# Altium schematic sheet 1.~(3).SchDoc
size 420 x 297 mm
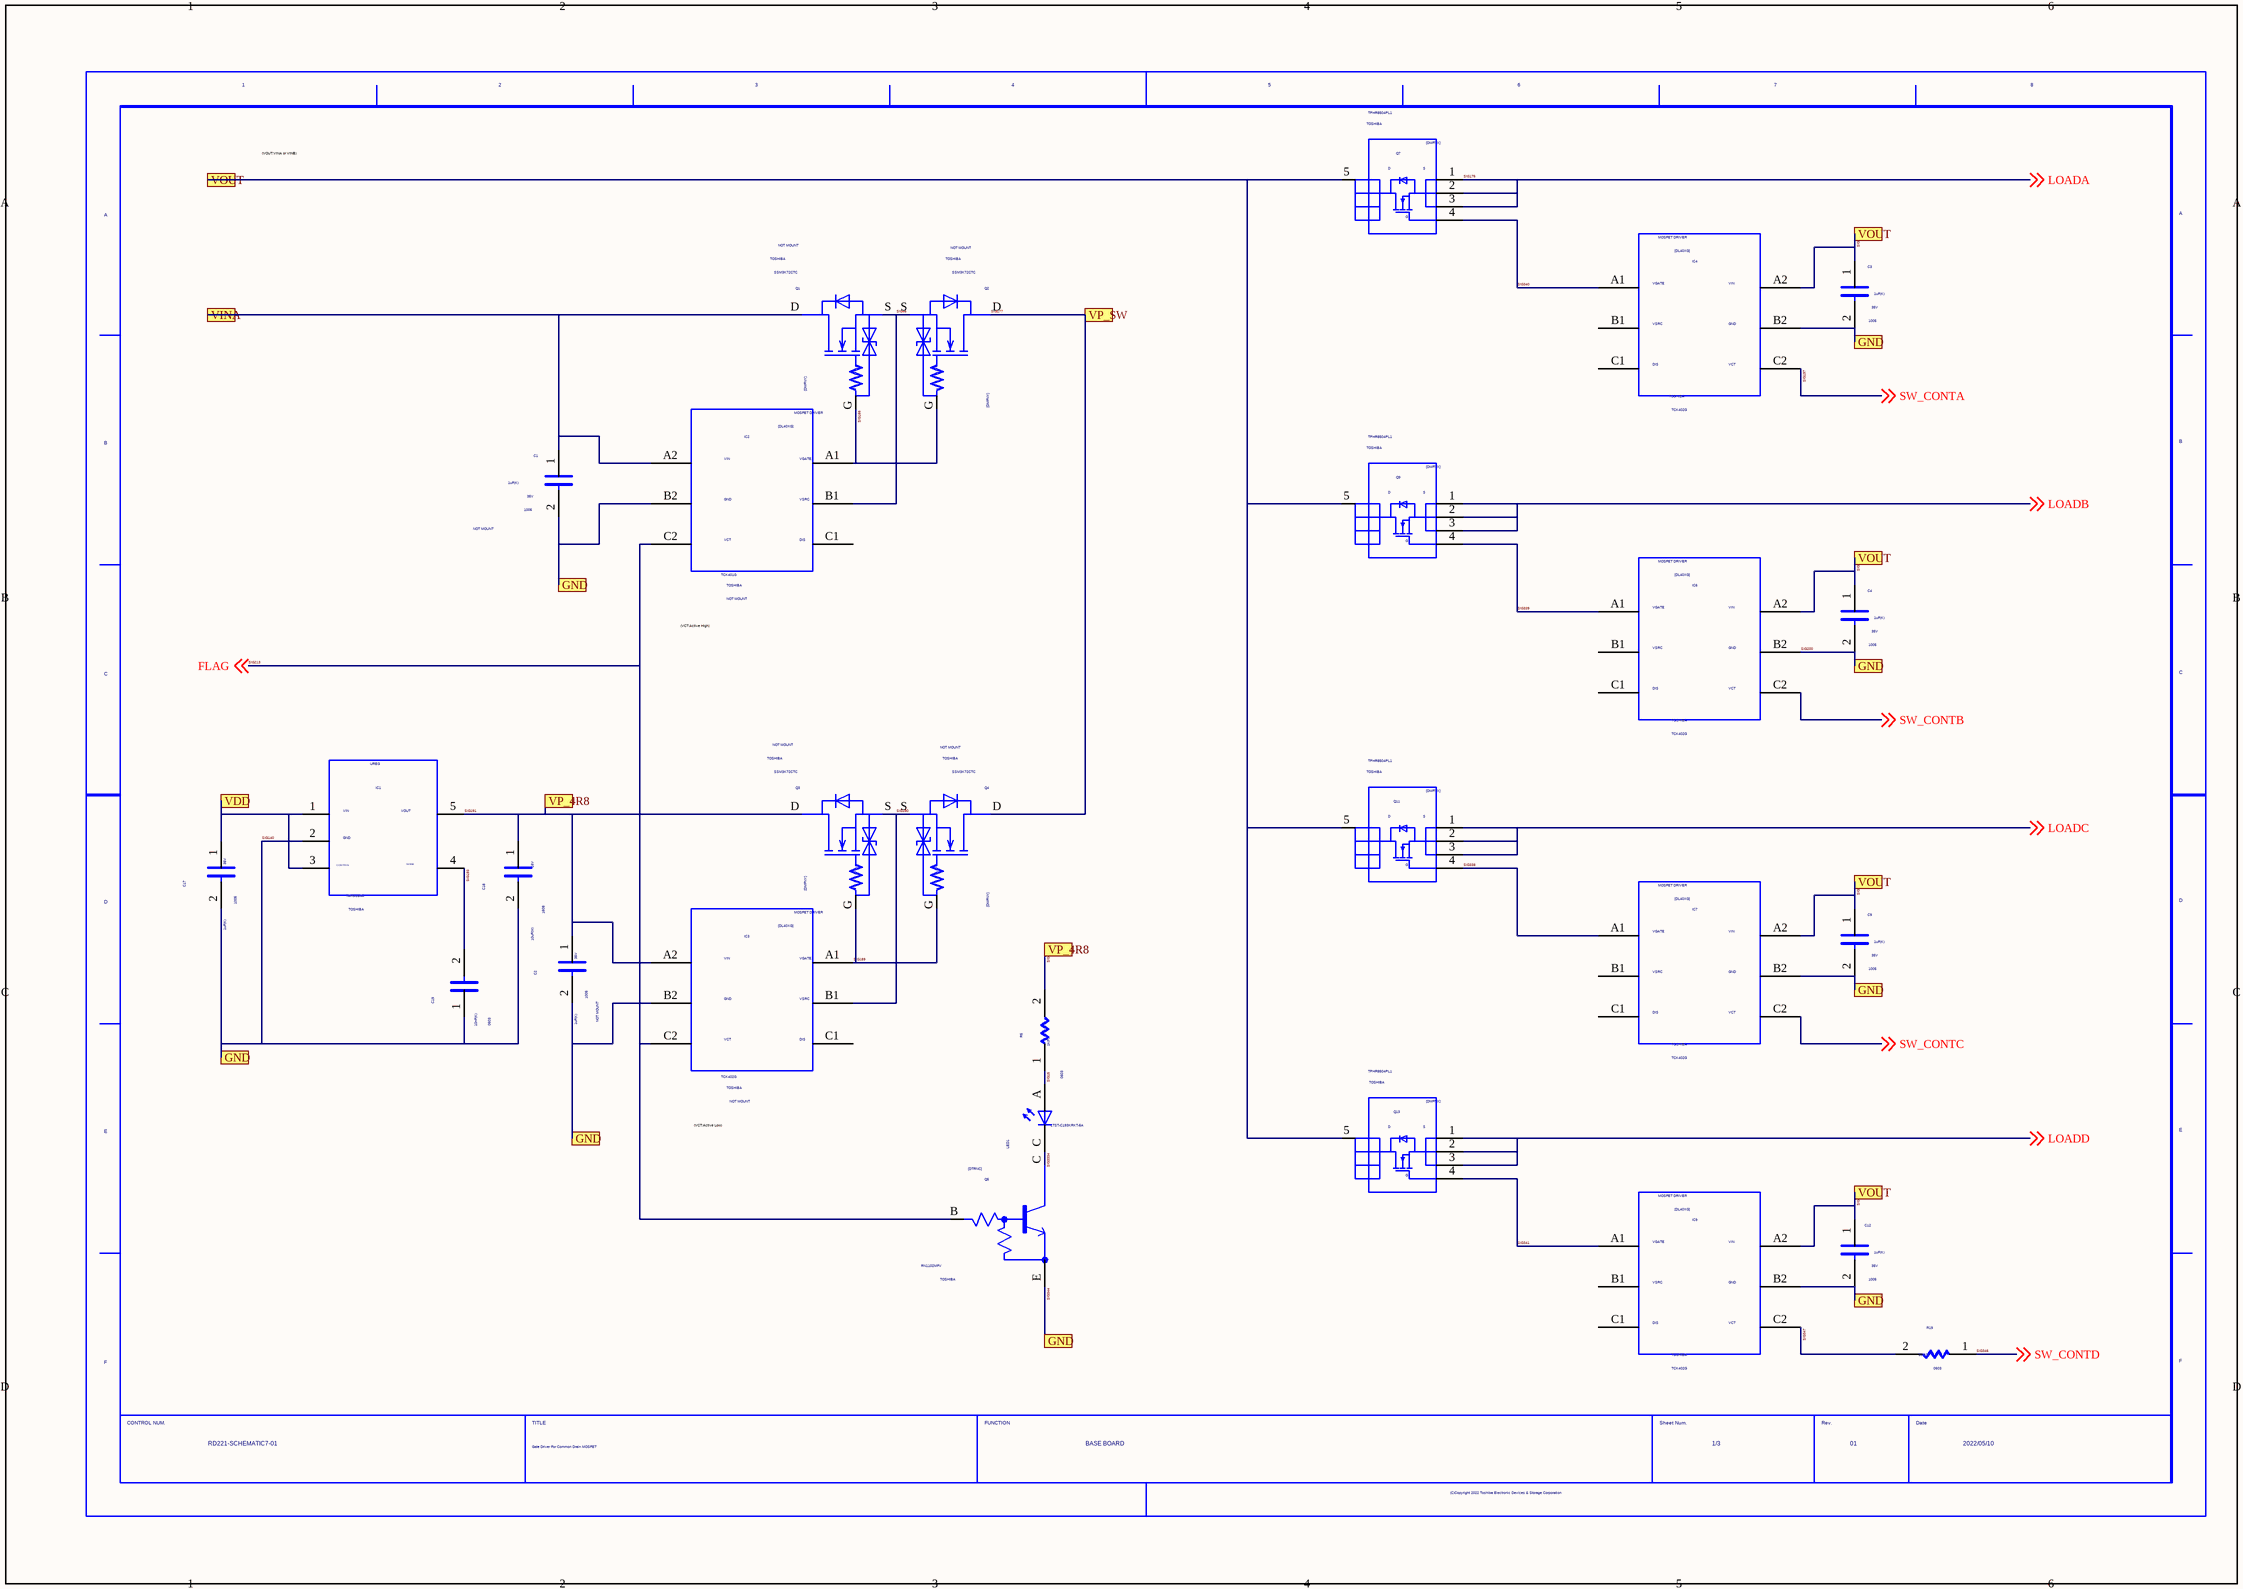
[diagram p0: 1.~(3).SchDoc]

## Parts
C1  NOTMOUNT: NOT MOUNT  SIZECODESMD: 1005  VAL2: 35V  VAL1: 1uF(K)  (hidden comment: DC)
C2  NOTMOUNT: NOT MOUNT  SIZECODESMD: 1005  VAL2: 35V  VAL1: 1uF(K)  (hidden comment: DC)
C3  SIZECODESMD: 1005  VAL2: 35V  VAL1: 1uF(K)  (hidden comment: DC)
C4  SIZECODESMD: 1005  VAL2: 35V  VAL1: 1uF(K)  (hidden comment: DC)
C9  SIZECODESMD: 1005  VAL2: 35V  VAL1: 1uF(K)  (hidden comment: DC)
C12  SIZECODESMD: 1005  VAL2: 35V  VAL1: 1uF(K)  (hidden comment: DC)
C17  SIZECODESMD: 1005  VAL2: 35V  VAL1: 1uF(K)  (hidden comment: DC)
C18  SIZECODESMD: 1608  VAL2: 16V  VAL1: 10uF(M)  (hidden comment: DC)
C19  SIZECODESMD: 0603  VAL1: 10nF(K)  (hidden comment: DC)
IC1  VAL1: TAR5SB48  USERCOMPTEXT3: TOSHIBA  (hidden comment: DL5SBXX)
IC2  NOTMOUNT: NOT MOUNT  VAL1: TCK401G  USERCOMPTEXT3: TOSHIBA  (hidden comment: DL40XG)
IC3  NOTMOUNT: NOT MOUNT  VAL1: TCK402G  USERCOMPTEXT3: TOSHIBA  (hidden comment: DL40XG)
IC4  VAL1: TCK402G  USERCOMPTEXT3: TOSHIBA  (hidden comment: DL40XG)
IC6  VAL1: TCK402G  USERCOMPTEXT3: TOSHIBA  (hidden comment: DL40XG)
IC7  VAL1: TCK402G  USERCOMPTEXT3: TOSHIBA  (hidden comment: DL40XG)
IC9  VAL1: TCK402G  USERCOMPTEXT3: TOSHIBA  (hidden comment: DL40XG)
LED1  VAL3: LTST-C193KRKT-5A  (hidden comment: DLED)
Q1  NOTMOUNT: NOT MOUNT  USERCOMPTEXT3: TOSHIBA  VAL1: SSM3K72CTC  (hidden comment: DMFNY)
Q2  NOTMOUNT: NOT MOUNT  USERCOMPTEXT3: TOSHIBA  VAL1: SSM3K72CTC  (hidden comment: DMFNY)
Q3  NOTMOUNT: NOT MOUNT  USERCOMPTEXT3: TOSHIBA  VAL1: SSM3K72CTC  (hidden comment: DMFNY)
Q4  NOTMOUNT: NOT MOUNT  USERCOMPTEXT3: TOSHIBA  VAL1: SSM3K72CTC  (hidden comment: DMFNY)
Q5  USERCOMPTEXT3: TOSHIBA  USERCOMPTEXT1: RN1102MFV  (hidden comment: DTRNC)
Q7  USERCOMPTEXT3: TOSHIBA  VAL1: TPHR8504PL1  (hidden comment: DMFNX)
Q9  USERCOMPTEXT3: TOSHIBA  VAL1: TPHR8504PL1  (hidden comment: DMFNX)
Q11  USERCOMPTEXT3: TOSHIBA  VAL1: TPHR8504PL1  (hidden comment: DMFNX)
Q13  USERCOMPTEXT3: TOSHIBA  VAL1: TPHR8504PL1  (hidden comment: DMFNX)
R5  SIZECODESMD: 0603  VAL1: 1k(F)  (hidden comment: DR)
R19  SIZECODESMD: 0603  VAL1: 100(J)  (hidden comment: DR)
U?  DATE: 2022/05/10  REVISION: 01  SHEETNUMBER: 1/3  FUNCTION: BASE BOARD  TITLE: Gate Driver For Common Drain MOSFET  DRAWINGNUMBER: RD221-SCHEMATIC7-01  (hidden comment: WAKU_DEF100)

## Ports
GND, VDD, VINA, VOUT, VP_4R8, VP_SW

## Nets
LOADB: Q9.1 Q9.2 Q9.3 ; off-sheet LOADB
LOADC: Q11.1 Q11.2 Q11.3 ; off-sheet LOADC
LOADD: Q13.1 Q13.2 Q13.3 ; off-sheet LOADD
SIG15: LED1.A R5.1
SIG46: IC2.B1 Q1.S Q2.S
SIG140: C1.2 C2.2 C3.2 C4.2 C9.2 C12.2 C17.2 C18.2 C19.1 IC1.2 IC2.B2 IC3.B2 IC4.B2 IC6.B2 IC7.B2 IC9.B2 Q5.E ; port GND  [also labelled SIG180, SIG188, SIG200, SIG203, SIG208, SIG344]
SIG166: IC2.A1 Q1.G Q2.G
SIG174: C3.1 C4.1 C9.1 C12.1 IC4.A2 IC6.A2 IC7.A2 IC9.A2 Q7.5 Q9.5 Q11.5 Q13.5 ; port VOUT  [also labelled SIG198, SIG204, SIG209]
SIG175: Q7.1 Q7.2 Q7.3 ; off-sheet LOADA  [also labelled LOADA]
SIG177: Q2.D Q4.D ; port VP_SW
SIG187: C17.1 IC1.1 IC1.3 ; port VDD
SIG189: IC3.A1 Q3.G Q4.G
SIG190: IC3.B1 Q3.S Q4.S
SIG191: C2.1 C18.1 IC1.5 IC3.A2 Q3.D R5.2 ; port VP_4R8  [also labelled SIG342]
SIG193: C19.2 IC1.4
SIG197: IC4.C2 ; off-sheet SW_CONTA  [also labelled SW_CONTA]
SIG213: IC2.C2 IC3.C2 Q5.B ; off-sheet FLAG  [also labelled FLAG]
SIG338: IC7.A1 Q11.4
SIG339: IC6.A1 Q9.4
SIG340: IC4.A1 Q7.4
SIG341: IC9.A1 Q13.4
SIG346: R19.1 ; off-sheet SW_CONTD  [also labelled SW_CONTD]
SIG347: IC9.C2 R19.2
SIG3334: LED1.C Q5.C
SW_CONTB: IC6.C2 ; off-sheet SW_CONTB
SW_CONTC: IC7.C2 ; off-sheet SW_CONTC
VINA: C1.1 IC2.A2 Q1.D ; port VINA

Not connected (* = marked no-connect by the designer): IC2 C1; IC3 C1; IC4 B1 C1; IC6 B1 C1; IC7 B1 C1; IC9 B1 C1

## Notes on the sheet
- (VOUT:VINA or VINB)
- (VCT:Active High)
- (VCT:Active Low)

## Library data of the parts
C1-C4 C9 C12 C17 = DC: OUMEPARTTYPE: C; OriginalSymbolOrigin: (2540,7620); FUNCN: DP0000016125; COMPONENTNAME: DP0000016125_package; MAXGCOUNT: 1; VAL3: GRM155R6YA105KE11D
C18 = DC: OUMEPARTTYPE: C; OriginalSymbolOrigin: (2540,7620); COMPONENTNAME: DP0008993000_package; MAXGCOUNT: 1; COMP: DP0008993000; VAL3: GRM188R61C106MA73D
C19 = DC: OUMEPARTTYPE: C; OriginalSymbolOrigin: (2540,7620); MAXGCOUNT: 1; COMPONENTNAME: DP0000015127; VAL3: GRM033B31C103KA12D; VAL2: 16V
IC1 = DL5SBXX: OUMEPARTTYPE: IC; SAVEAREA0: -49052,-25553,79781,45765; SAVECOUNT: 22; TIME: 15:23:15; UPDATEUSER: t5459927; UPDATETIME: 15:26:52; OriginalSymbolOrigin: (5080,25400); FUNCN: DP0010569000; COMPONENTNAME: DP0010569000_package; MAXGCOUNT: 1
IC2 = DL40XG: OUMEPARTTYPE: IC; SAVEAREA0: -25087,-13639,60802,33906; TIME: 11:49:52; UPDATEUSER: t5459927; UPDATETIME: 14:00:32; SAVECOUNT: 26; OriginalSymbolOrigin: (7620,30480); FUNCN: DP0010565000; COMPONENTNAME: DP0010565000_package; MAXGCOUNT: 1
IC3 IC4 IC6 IC7 IC9 = DL40XG: OUMEPARTTYPE: IC; SAVEAREA0: -25087,-13639,60802,33906; TIME: 11:49:52; UPDATEUSER: t5459927; UPDATETIME: 14:00:32; SAVECOUNT: 26; OriginalSymbolOrigin: (7620,30480); FUNCN: DP0010566000; COMPONENTNAME: DP0010566000_package; MAXGCOUNT: 1
LED1 = DLED: OUMEPARTTYPE: DS; SAVEAREA0: -6799,-183,19247,15664; TIME: 14:49:55; UPDATEUSER: fukuda-y; UPDATETIME: 13:54:07; SAVECOUNT: 4; OriginalSymbolOrigin: (5080,7620); COMPONENTNAME: DP0010573000_package; MAXGCOUNT: 1; COMP: DP0010573000
Q1-Q4 = DMFNY: PARTS: 1; OUMEPARTTYPE: Q; SAVECOUNT: 28; SAVEAREA0: -23889,-10269,46852,25387; TIME: 08:01:03; UPDATEUSER: w90028dm; UPDATETIME: 15:04:53; HETERO: RN4905_1,RN4905_2; FUNCTION: PNP&NPN_PCT; LEVEL: STD; PKG_TYPE: 2-2J1A; DEVICE: RN4905; DEVICENAME: RN49A1FE(TE85L); OriginalSymbolOrigin: (2540,15240); COMPONENTNAME: DP0010564000_package; COMP: DP0010564000
Q5 = DTRNC: OUMEPARTTYPE: Q; SAVEAREA0: -25957,-6856,48160,30039; TIME: 14:43:11; UPDATEUSER: w90028dm; UPDATETIME: 10:13:46; SAVECOUNT: 5; OriginalSymbolOrigin: (2540,22860); COMPONENTNAME: DP0010015000_package; MAXGCOUNT: 1; COMP: DP0010015000; VAL3: RN1114MFV
Q7 Q9 Q11 Q13 = DMFNX: OUMEPARTTYPE: Q; SAVEAREA0: -12700,-263,35150,23556; TIME: 18:57:44; UPDATEUSER: 19990028; UPDATETIME: 11:40:13; SAVECOUNT: 15; OriginalSymbolOrigin: (5080,20320); COMPONENTNAME: DP0010567000_package; MAXGCOUNT: 1; COMP: DP0010567000
R5 = DR: OUMEPARTTYPE: R; OriginalSymbolOrigin: (5080,5080); MAXGCOUNT: 1; COMPONENTNAME: DP0000152048; VAL3: ERJ1GNF1001C; VAL2: 50mW
R19 = DR: OUMEPARTTYPE: R; OriginalSymbolOrigin: (5080,5080); MAXGCOUNT: 1; COMPONENTNAME: DP0000155000_package; COMP: DP0000155000; VAL3: RK73B1HTTC101J; VAL2: 50mW
U? = WAKU_DEF100: PLOTTIME: HH:MM; SAVEAREA0: 148187,-66180,486823,89919; TIME: 14:30:25; UPDATEUSER: t5459927; UPDATETIME: 07:15:59; SAVECOUNT: 6; OriginalSymbolOrigin: (10160,284480)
